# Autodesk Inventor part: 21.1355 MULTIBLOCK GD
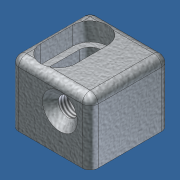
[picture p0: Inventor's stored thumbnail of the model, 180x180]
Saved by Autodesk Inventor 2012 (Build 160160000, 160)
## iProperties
Created: 2007-04
Part Number: 21.1355 MULTIBLOCK GD
Document SubType Name: Modeling
Designer: Andy Moles
Material: Aluminum-6061
Density: 2.71 g/cm^3
Mass: 23.5416 g
Surface Area: 41.1787 cm^2
Volume: 8.68694 cm^3
Author: Andy Moles
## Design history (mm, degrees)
sketch "Sketch1"
  geometry: L1 (-10, -12.5)-(10, -12.5); L2 (12.5, -10)-(12.5, 10); L3 (10, 12.5)-(-10, 12.5); L4 (-12.5, 10)-(-12.5, -10); L5 (-8.5, -5)-(-8.5, 5); L6 (-1.5, -5)-(-1.5, 5); A1 r 2.5 centre (-10, 10) between (-10, 12.5) and (-12.5, 10); A2 r 2.5 centre (10, 10) between (12.5, 10) and (10, 12.5); A3 r 2.5 centre (10, -10) between (10, -12.5) and (12.5, -10); A4 r 2.5 centre (-10, -10) between (-12.5, -10) and (-10, -12.5); A5 r 3.5 centre (-5, 5) between (-1.5, 5) and (-8.5, 5); A6 r 3.5 centre (-5, -5) between (-8.5, -5) and (-1.5, -5); 4 further points
  constraints: 12 end point, 12 point on circle, 10 tangent, 6 centre point, 4 parallel, 3 equal radius, 3 midpoint, 2 horizontal alignment, 2 vertical alignment, 1 horizontal, 1 perpendicular
  dimensions: "d0" = 2.5 radius of A1; "d1" = 25 distance between parallel lines of L2 L4; "d2" = 25 distance between parallel lines of L1 L3; "d3" = 7 diameter of A5; "d4" = 7 diameter of A6; "d5" = 17 dimension on A6 A5; "d6" = 17.5 distance from line of A5.centre L2
extrude "Extrusion1" new body sketch "Sketch1" distance "d7" = 20; taper "d8" = 0 deg
sketch "Sketch2"
  geometry: L1 (-8.5, -5)-(-8.5, 5) reference; L2 (-1.5, 5)-(-1.5, -5) reference; L3 (12.5, 10)-(12.5, -10) reference; L4 (-10.5, -5)-(-10.5, 5); L5 (0.5, -5)-(0.5, 5); A1 r 3.5 centre (-5, 5) between (-1.5, 5) and (-8.5, 5) reference; A2 r 3.5 centre (-5, -5) between (-8.5, -5) and (-1.5, -5) reference; A3 r 5.5 centre (-5, -5) between (-10.5, -5) and (0.5, -5); A4 r 5.5 centre (-5, 5) between (0.5, 5) and (-10.5, 5); 1 further point
  constraints: 4 end point, 4 point on circle, 2 centre point, 2 coincident, 2 parallel, 2 tangent
extrude "Extrusion2" cut sketch "Sketch2" distance "d11" = 5.75; taper "d12" = 0 deg
hole "Hole1" diameter "d15" = 6; stored, may be unused: countersink angle "d19" = 90 deg, drill point angle "d21" = 118 deg; dims "d13" = 12, "d14" = 9.5, "d16" = 6, "d17" = 11, "d18" = 2, "d20" = 8
hole "Hole2" diameter "d24" = 6; stored, may be unused: countersink angle "d28" = 90 deg, drill point angle "d30" = 118 deg; dims "d22" = 12, "d23" = 9.5, "d25" = 6, "d26" = 11, "d27" = 2, "d29" = 8
fillet "Fillet1" dims "d31" = 2.5
thread "Thread1" dims "d32" = 10, "d33" = 0
body "Solid1"
other parameters: "d9" = 11, "d10" = 11
